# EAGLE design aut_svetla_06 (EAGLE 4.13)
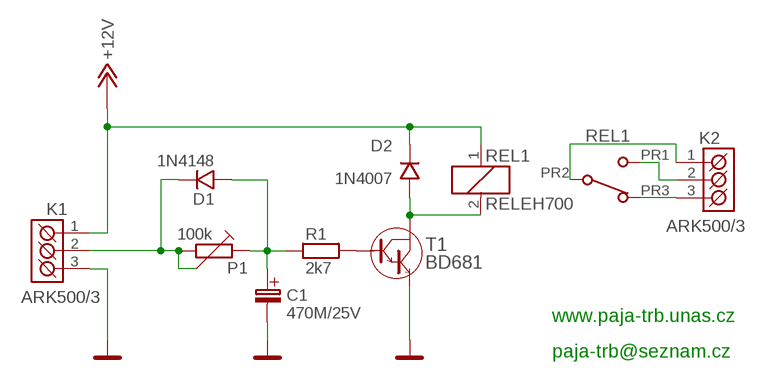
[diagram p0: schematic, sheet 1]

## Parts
C1  470M/25V  [C_EL_5]
D1  1N4148  1N4148_7,5  [D-7,5]
D2  1N4007  1N4007_10  [D-10]
K1  ARK500/3  [ARK500/3]
K2  ARK500/3  [ARK500/3]
P1  100k  PT-10_V-LEZ  [PT10V]
R1  2k7  R_7,5  [R-7,5]
REL1  RELEH700  [RELEH700]
T1  BD681  BD681_STOJ  [TO-126S]

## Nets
+12V: D2.K K1.1(K1) REL1.1(CIVKA:C1)
GND: C1.C-(C_EL-) K1.3(K3) T1.1(E)
N$1: D1.K K1.2(K2) P1.2 P1.3
N$2: C1.C+(C_EL+) D1.A P1.1 R1.1
N$3: D2.A REL1.2(CIVKA:C2) T1.2(C)
N$4: K2.2(K2) REL1.PR1(PREP:NO)
N$5: K2.3(K3) REL1.PR3(PREP:NC)
N$6: K2.1(K1) REL1.PR2(PREP:COM)
N$7: R1.2 T1.3(B)

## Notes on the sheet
- www.paja-trb.unas.cz
- paja-trb@seznam.cz

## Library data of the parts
C1 = #PaJa_C-el:470M/25V
D1 = #PaJa_17:1N4148: Univerzalni dioda - 0,15A, 75V
D2 = #PaJa_17:1N4007: Usmernovaci dioda - 1A, 1000V
K1 K2 = #PaJa_17:ARK500/3: Svorkovnice - roztec 5mm - trojita
P1 = #PaJa_17:PT-10: Trimr - 10,3mm
R1 = #PaJa_17:R: Rezistor
REL1 = #PaJa_17:RELEH700
T1 = #PaJa_17:BD681

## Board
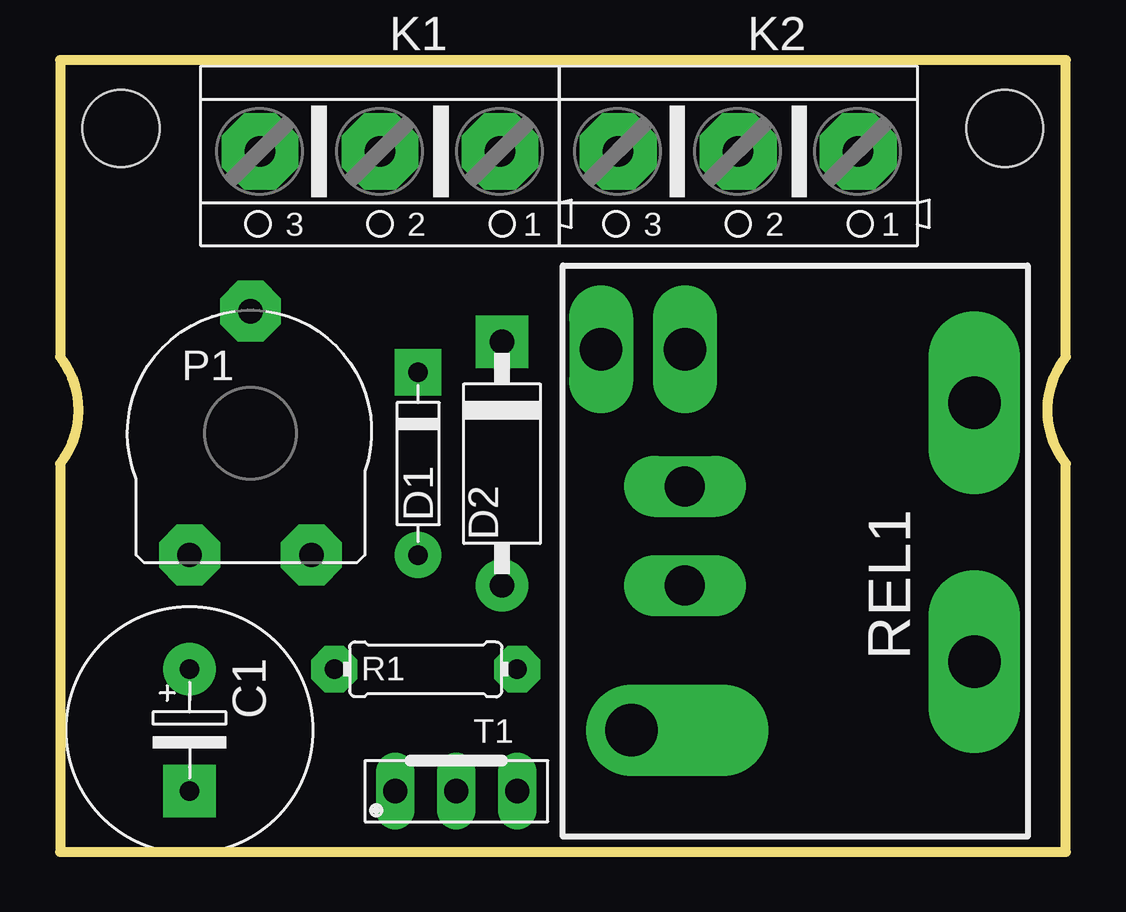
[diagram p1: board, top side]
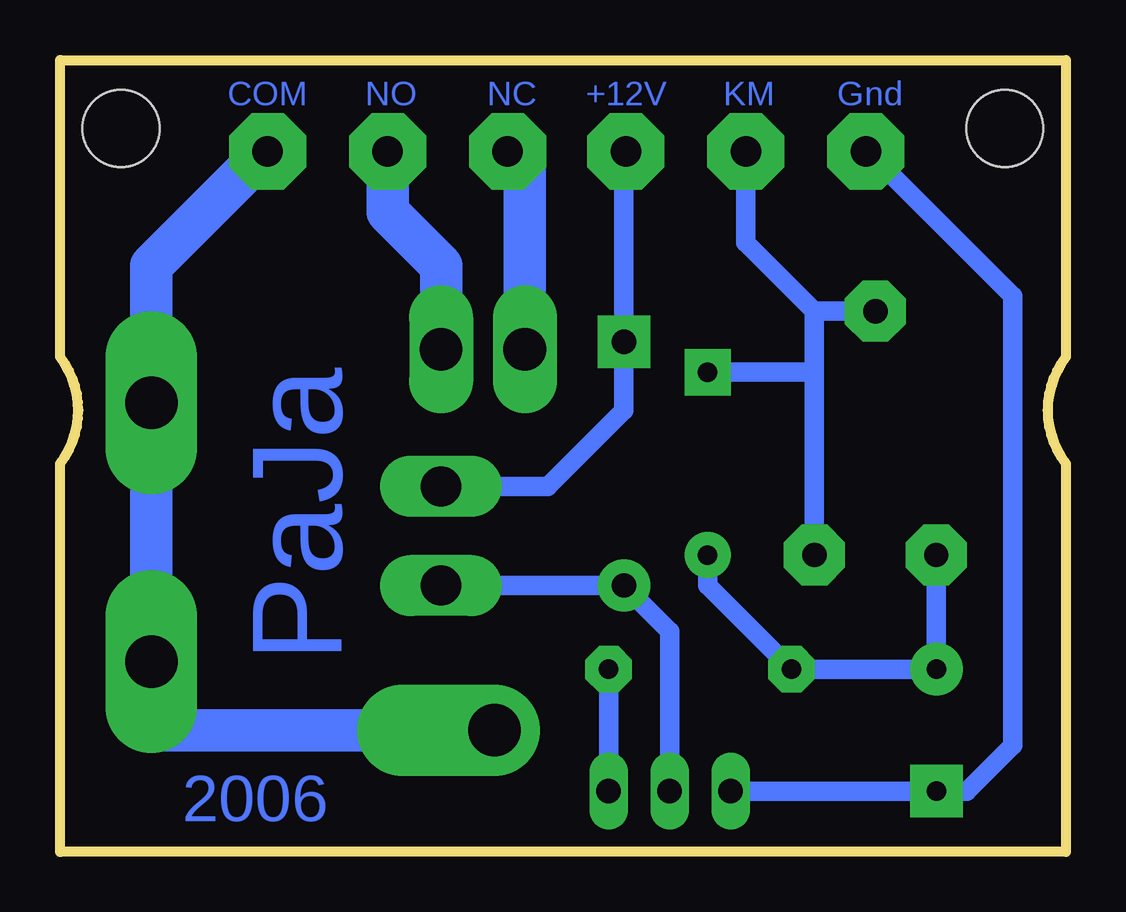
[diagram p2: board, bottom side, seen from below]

Size 41.91 x 33.02 mm. Coordinates in mm from the lower left corner, seen from the top.
Outline: 41.9,0 0,0 0,16.19 arc76 0,20.64 0,33.01 41.9,33.01
Outline: 41.91,0 41.91,16.19 arc-76 41.91,20.64 41.91,33.02
Copper layers (1*16): Top 0.035mm / dielectric 1.5mm / Bottom 0.035mm
Design rules "default": minimum track width 10mil, minimum drill 24mil, track to track 8mil, track to pad 8mil, pad to pad 8mil, via to via 8mil, smd to smd 8mil, copper to edge 40mil, drill to drill 8mil, minimum pad ring 10mil, minimum via ring 8mil, stop-mask expansion 4mil, vias tented up to drill 0mil, thermal gap 10mil
Holes 3.2 mm at 2.54,30.16 39.37,30.16

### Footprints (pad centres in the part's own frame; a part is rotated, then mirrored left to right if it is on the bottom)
C_EL_5 = drill 0.813 pad 2.184 round: C+ -2.54,0 | drill 0.813 pad 2.184 square: C- 2.54,0
D-7,5 = drill 0.813 pad 1.93 round: A -3.81,0 | drill 0.813 pad 1.93 square: K 3.81,0
D-10 = drill 1.016 pad 2.184 round: A -5.08,0 | drill 1.016 pad 2.184 square: K 5.08,0
ARK500/3 = drill 1.27 pad 3.2 octagon: 1 -5,0; 2 0,0; 3 5,0
PT10V = drill 1.016 pad 2.54 octagon: 1 -2.54,-5.08; 2 2.54,-5.08; 3 0,5.08
R-7,5 = drill 0.813 pad 1.93 octagon: 1 -3.81,0; 2 3.81,0
RELEH700 = drill 1.676 pad 2.54 long: 1 -2.857,-4.763; 2 1.27,-4.763 | drill 1.778 pad 2.54 long: PR1 -8.572,-4.763; PR3 -8.572,-8.255 | drill 2.184 pad 3.81 long: PR2 -6.35,7.303; PR2A 4.445,7.303 | drill 2.184 pad 3.81 offset: PR2B 7.303,-6.985
TO-126S = drill 1.016 pad 1.6 long: 1 -2.54,0; 2 0,0; 3 2.54,0

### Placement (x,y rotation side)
C1  5.4,5.08 270 top
D1  14.92,16.19 90 top
D2  18.41,16.19 90 top
K1  13.34,29.21 180 top
K2  28.26,29.21 180 top
P1  7.94,17.46 0 top
R1  15.24,7.62 0 top
REL1  30.8,12.38 270 top
T1  16.51,2.54 0 top

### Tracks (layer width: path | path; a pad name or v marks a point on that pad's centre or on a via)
+12V
  Bottom 0.813: REL1.1 21.59,15.24 18.41,18.41 D2.K 18.41,29.21 K1.1
GND
  Bottom 0.813: T1.1 C1.C- 4.13,2.54 2.22,4.45 2.22,23.18 8.26,29.21 K1.3
N$1
  Bottom 0.813: P1.2 10.48,20 | 10.48,22.54 P1.3 | 10.48,20 D1.K | 10.48,20 10.48,22.54 | 10.48,22.54 13.34,25.4 K1.2
N$2
  Bottom 0.813: P1.1 C1.C+ R1.1 14.92,11.11 D1.A
N$3
  Bottom 0.813: T1.2 16.51,9.21 D2.A REL1.2
N$4
  Bottom 1.778: REL1.PR1 26.04,24.45 28.26,26.67 K2.2
N$5
  Bottom 1.778: K2.3 23.18,29.21 22.54,28.57 REL1.PR3
N$6
  Bottom 1.778: 23.81,5.08 38.1,5.08 REL1.PR2 38.1,20.64 38.1,24.45 33.34,29.21
  Bottom 1.93: 33.34,29.21 K2.1
N$7
  Bottom 0.813: T1.3 R1.2

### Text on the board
Bottom: Gnd | KM | +12V | NC | NO | COM | PaJa | 2006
